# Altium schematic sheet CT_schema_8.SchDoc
size 274 x 160 mm
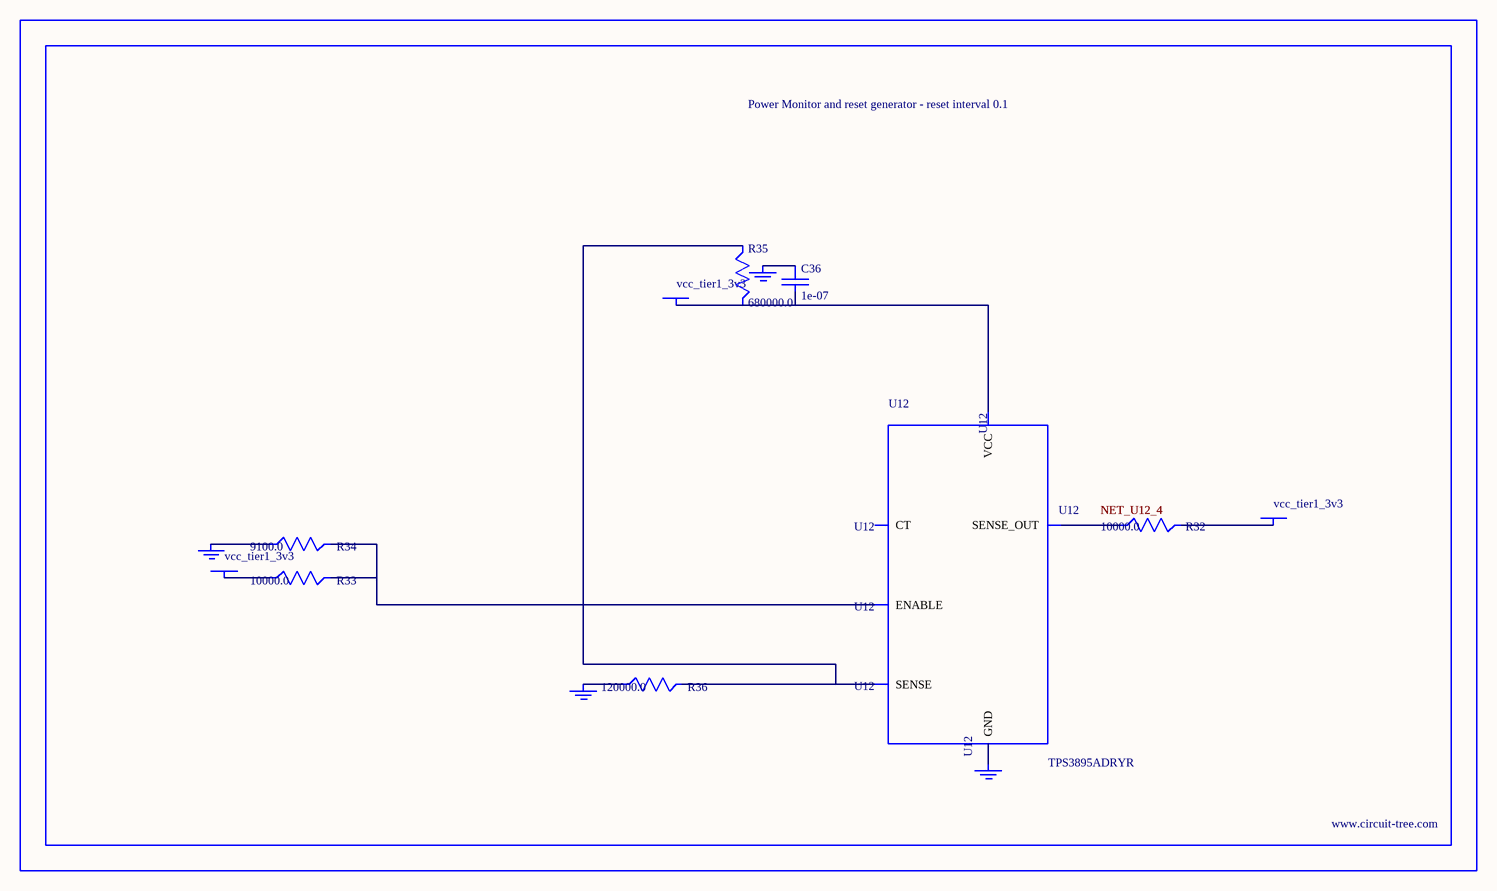
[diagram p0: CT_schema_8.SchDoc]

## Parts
BORDER7  (no value)
C36  1e-07  [C0402]
GND_INSTANCE_7_0  (no value)
GND_INSTANCE_7_1  (no value)
GND_INSTANCE_7_2  (no value)
GND_INSTANCE_7_3  (no value)
POWER_INSTANCE_7_0  vcc_tier1_3v3
POWER_INSTANCE_7_1  vcc_tier1_3v3
POWER_INSTANCE_7_2  vcc_tier1_3v3
R32  10000.0  [R0603]
R33  10000.0  [R0603]
R34  9100.0  [R0603]
R35  680000.0  [R0603]
R36  120000.0  [R0603]
U12  TPS3895ADRYR  [SON-6]

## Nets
NetC36_1: C36.1 GND_INSTANCE_7_2.0(GND)
NetC36_2: C36.2 POWER_INSTANCE_7_2.0(PWR) R35.2 U12.6(VCC)
NetGND_INSTANCE_7_0_0: GND_INSTANCE_7_0.0(GND) R34.1
NetGND_INSTANCE_7_1_0: GND_INSTANCE_7_1.0(GND) R36.1
NetGND_INSTANCE_7_3_0: GND_INSTANCE_7_3.0(GND) U12.2(GND)
NetPOWER_INSTANCE_7_0_0: POWER_INSTANCE_7_0.0(PWR) R33.1
NetPOWER_INSTANCE_7_1_0: POWER_INSTANCE_7_1.0(PWR) R32.2
NetR32_1: R32.1 U12.4(SENSE_OUT)
NetR33_2: R33.2 R34.2 U12.1(ENABLE)
NetR35_1: R35.1 R36.2 U12.3(SENSE)

Not connected (* = marked no-connect by the designer): U12 5(CT)

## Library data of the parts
BORDER7 = BORDER_PAGE7
C36 = C0402C104K3RACTU
GND_INSTANCE_7_0-GND_INSTANCE_7_3 = GND
POWER_INSTANCE_7_0-POWER_INSTANCE_7_2 = PWR
R32 R33 = RC0603JR-0710KL
R34 = RC0603JR-079K1L
R35 = RC0603JR-07680KL
R36 = RC0603JR-07120KL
